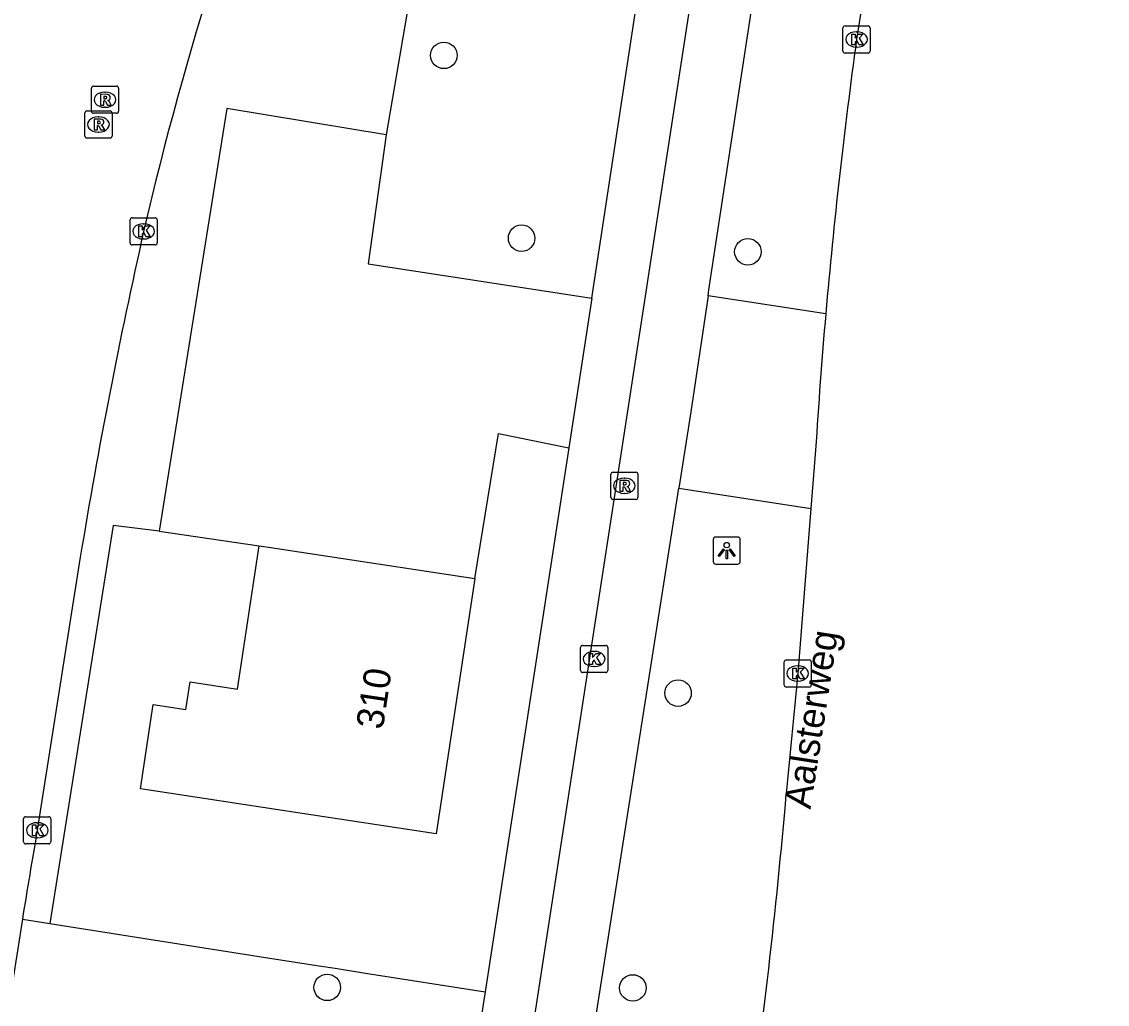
# Model space of a CAD drawing. Extents: x 161094 to 161705, y 379509 to 380907.
# Drawn here: x 161594.33 to 161634.35, y 380358.54 to 380394.77 of the extents above; entities that cross this region are included whole.
import ezdxf

# ---------------------------------------------------------------- set-up
doc = ezdxf.new("R2010")
doc.units = 0
for name, color, linetype in [('IMGEO_Berm_groen', 7, 'Continuous'), ('IMGEO_Boom', 7, 'Continuous'), ('IMGEO_Fietspad_gesloten', 7, 'Continuous'), ('IMGEO_Kolk', 7, 'Continuous'), ('IMGEO_Lichtpunt', 7, 'Continuous'), ('IMGEO_Openbare_ruimte_label', 7, 'Continuous'), ('IMGEO_OVBaan_gesloten', 7, 'Continuous'), ('IMGEO_Pand', 7, 'Continuous'), ('IMGEO_Pand_nummerreeks', 7, 'Continuous'), ('IMGEO_Parkeervlak_open', 7, 'Continuous'), ('IMGEO_Rijbaan_lokaal_open', 7, 'Continuous'), ('IMGEO_Rijbaan_regionaal_gesloten', 7, 'Continuous'), ('IMGEO_Rioolput', 7, 'Continuous'), ('IMGEO_Voetpad_open', 7, 'Continuous')]:
    doc.layers.add(name, color=color, linetype=linetype)

msp = doc.modelspace()

# ---------------------------------------------------------------- linework, layer by layer
at = {"layer": 'IMGEO_Berm_groen'}
for points in [[(161613.791, 380425.771), (161607.762, 380390.596)], [(161599.392, 380375.982), (161597.696, 380376.197), (161595.362, 380361.521)], [(161594.355, 380361.681), (161595.362, 380361.521)], [(161595.362, 380361.521), (161603.085, 380360.307), (161605.209, 380359.973), (161605.886, 380359.866), (161606.999, 380359.691), (161611.414, 380358.997)]]:
    msp.add_lwpolyline(points, dxfattribs=at)
at = {"layer": 'IMGEO_Boom'}
for centre in [(161609.893, 380393.524), (161612.76, 380386.784), (161621.103, 380386.282), (161618.528, 380370.013), (161605.594, 380359.163), (161616.859, 380359.142)]:
    msp.add_circle(centre, 0.489, dxfattribs=at)
at = {"layer": 'IMGEO_Fietspad_gesloten'}
for points in [[(161610.539, 380340.52), (161610.562, 380340.668), (161611.943, 380349.647), (161622.87, 380420.7), (161623.371, 380423.923)], [(161619.636, 380384.663), (161619.668, 380384.881), (161622.43, 380403.035), (161622.852, 380405.923), (161625.07, 380420.051), (161625.649, 380423.882)], [(161608.177, 380310.609), (161612.498, 380338.392), (161614.175, 380349.387), (161615.522, 380358.208), (161618.561, 380377.574)]]:
    msp.add_lwpolyline(points, dxfattribs=at)
at = {"layer": 'IMGEO_Kolk'}
for p, q in [((161624.683, 380394.611), (161625.535, 380394.611)), ((161624.608, 380393.685), (161624.608, 380394.537)), ((161625.096, 380394.391), (161625.121, 380394.391)), ((161625.609, 380394.537), (161625.609, 380393.685)), ((161625.119, 380393.831), (161625.094, 380393.831)), ((161625.535, 380393.611), (161624.683, 380393.611)), ((161598.324, 380386.609), (161598.324, 380387.461)), ((161598.399, 380387.535), (161599.251, 380387.535)), ((161599.325, 380387.461), (161599.325, 380386.609)), ((161598.812, 380387.315), (161598.837, 380387.315)), ((161598.835, 380386.755), (161598.81, 380386.755)), ((161599.251, 380386.535), (161598.399, 380386.535)), ((161615.008, 380371.772), (161615.86, 380371.772)), ((161614.933, 380370.846), (161614.933, 380371.698)), ((161615.421, 380371.552), (161615.446, 380371.552)), ((161615.934, 380371.698), (161615.934, 380370.846)), ((161615.444, 380370.992), (161615.419, 380370.992)), ((161622.44, 380370.31), (161622.44, 380371.162)), ((161622.515, 380371.236), (161623.367, 380371.236)), ((161622.928, 380371.016), (161622.953, 380371.016)), ((161623.441, 380371.162), (161623.441, 380370.31)), ((161615.86, 380370.772), (161615.008, 380370.772)), ((161623.367, 380370.236), (161622.515, 380370.236)), ((161622.951, 380370.456), (161622.926, 380370.456)), ((161594.401, 380364.528), (161594.401, 380365.38)), ((161594.476, 380365.454), (161595.328, 380365.454)), ((161595.402, 380365.38), (161595.402, 380364.528)), ((161594.889, 380365.234), (161594.914, 380365.234)), ((161594.912, 380364.674), (161594.887, 380364.674)), ((161595.328, 380364.454), (161594.476, 380364.454))]:
    msp.add_line(p, q, dxfattribs=at)
for points in [[(161624.683, 380394.611), (161625.535, 380394.611)], [(161624.608, 380393.685), (161624.608, 380394.537)], [(161624.929, 380394.311), (161625.052, 380394.311), (161625.052, 380394.16), (161625.182, 380394.311), (161625.346, 380394.311), (161625.2, 380394.16), (161625.353, 380393.911), (161625.201, 380393.911), (161625.116, 380394.075), (161625.052, 380394.008), (161625.052, 380393.911), (161624.929, 380393.911), (161624.929, 380394.311)], [(161625.609, 380394.537), (161625.609, 380393.685)], [(161625.535, 380393.611), (161624.683, 380393.611)], [(161598.324, 380386.609), (161598.324, 380387.461)], [(161598.399, 380387.535), (161599.251, 380387.535)], [(161599.325, 380387.461), (161599.325, 380386.609)], [(161598.645, 380387.235), (161598.768, 380387.235), (161598.768, 380387.084), (161598.898, 380387.235), (161599.062, 380387.235), (161598.916, 380387.084), (161599.069, 380386.835), (161598.917, 380386.835), (161598.832, 380386.999), (161598.768, 380386.932), (161598.768, 380386.835), (161598.645, 380386.835), (161598.645, 380387.235)], [(161599.251, 380386.535), (161598.399, 380386.535)], [(161615.008, 380371.772), (161615.86, 380371.772)], [(161614.933, 380370.846), (161614.933, 380371.698)], [(161615.254, 380371.472), (161615.377, 380371.472), (161615.377, 380371.321), (161615.507, 380371.472), (161615.671, 380371.472), (161615.525, 380371.321), (161615.678, 380371.072), (161615.526, 380371.072), (161615.441, 380371.236), (161615.377, 380371.169), (161615.377, 380371.072), (161615.254, 380371.072), (161615.254, 380371.472)], [(161615.934, 380371.698), (161615.934, 380370.846)], [(161622.44, 380370.31), (161622.44, 380371.162)], [(161622.515, 380371.236), (161623.367, 380371.236)], [(161623.441, 380371.162), (161623.441, 380370.31)], [(161615.86, 380370.772), (161615.008, 380370.772)], [(161622.761, 380370.936), (161622.884, 380370.936), (161622.884, 380370.785), (161623.014, 380370.936), (161623.178, 380370.936), (161623.032, 380370.785), (161623.185, 380370.536), (161623.033, 380370.536), (161622.948, 380370.7), (161622.884, 380370.633), (161622.884, 380370.536), (161622.761, 380370.536), (161622.761, 380370.936)], [(161623.367, 380370.236), (161622.515, 380370.236)], [(161594.401, 380364.528), (161594.401, 380365.38)], [(161594.476, 380365.454), (161595.328, 380365.454)], [(161595.402, 380365.38), (161595.402, 380364.528)], [(161594.722, 380365.154), (161594.845, 380365.154), (161594.845, 380365.003), (161594.975, 380365.154), (161595.139, 380365.154), (161594.993, 380365.003), (161595.146, 380364.754), (161594.994, 380364.754), (161594.909, 380364.918), (161594.845, 380364.851), (161594.845, 380364.754), (161594.722, 380364.754), (161594.722, 380365.154)], [(161595.328, 380364.454), (161594.476, 380364.454)]]:
    msp.add_lwpolyline(points, dxfattribs=at)
for centre, start, end in [((161624.685, 380394.535), 91.552, 178.448), ((161624.685, 380394.535), 91.552, 178.448), ((161625.533, 380394.535), 1.552, 88.448), ((161625.533, 380394.535), 1.552, 88.448), ((161624.685, 380393.687), 181.552, 268.448), ((161624.685, 380393.687), 181.552, 268.448), ((161625.533, 380393.687), 271.552, 358.448), ((161625.533, 380393.687), 271.552, 358.448), ((161598.401, 380387.459), 91.552, 178.448), ((161598.401, 380387.459), 91.552, 178.448), ((161599.249, 380387.459), 1.552, 88.448), ((161599.249, 380387.459), 1.552, 88.448), ((161598.401, 380386.611), 181.552, 268.448), ((161598.401, 380386.611), 181.552, 268.448), ((161599.249, 380386.611), 271.552, 358.448), ((161599.249, 380386.611), 271.552, 358.448), ((161615.01, 380371.696), 91.552, 178.448), ((161615.01, 380371.696), 91.552, 178.448), ((161615.858, 380371.696), 1.552, 88.448), ((161615.858, 380371.696), 1.552, 88.448), ((161622.517, 380371.16), 91.552, 178.448), ((161622.517, 380371.16), 91.552, 178.448), ((161623.365, 380371.16), 1.552, 88.448), ((161623.365, 380371.16), 1.552, 88.448), ((161615.01, 380370.848), 181.552, 268.448), ((161615.01, 380370.848), 181.552, 268.448), ((161615.858, 380370.848), 271.552, 358.448), ((161615.858, 380370.848), 271.552, 358.448), ((161622.517, 380370.312), 181.552, 268.448), ((161622.517, 380370.312), 181.552, 268.448), ((161623.365, 380370.312), 271.552, 358.448), ((161623.365, 380370.312), 271.552, 358.448), ((161594.478, 380365.378), 91.552, 178.448), ((161594.478, 380365.378), 91.552, 178.448), ((161595.326, 380365.378), 1.552, 88.448), ((161595.326, 380365.378), 1.552, 88.448), ((161594.478, 380364.53), 181.552, 268.448), ((161594.478, 380364.53), 181.552, 268.448), ((161595.326, 380364.53), 271.552, 358.448), ((161595.326, 380364.53), 271.552, 358.448)]:
    msp.add_arc(centre, 0.0765, start, end, dxfattribs=at)
for centre, major_axis, ratio, start_param, end_param in [((161625.095, 380394.111), (-0.387, 0.002), 0.722429, 4.712389, 7.853982), ((161625.12, 380394.111), (-0.39, 0.002), 0.717154, 1.570796, 4.712389), ((161598.811, 380387.035), (-0.387, 0.002), 0.722429, 4.712389, 7.853982), ((161598.836, 380387.035), (-0.39, 0.002), 0.717154, 1.570796, 4.712389), ((161615.42, 380371.272), (-0.387, 0.002), 0.722429, 4.712389, 7.853982), ((161615.445, 380371.272), (-0.39, 0.002), 0.717154, 1.570796, 4.712389), ((161622.927, 380370.736), (-0.387, 0.002), 0.722429, 4.712389, 7.853982), ((161622.952, 380370.736), (-0.39, 0.002), 0.717154, 1.570796, 4.712389), ((161594.888, 380364.954), (-0.387, 0.002), 0.722429, 4.712389, 7.853982), ((161594.913, 380364.954), (-0.39, 0.002), 0.717154, 1.570796, 4.712389)]:
    msp.add_ellipse(centre, major_axis=major_axis, ratio=ratio, start_param=start_param, end_param=end_param, dxfattribs=at)
at = {"layer": 'IMGEO_Lichtpunt'}
for p, q in [((161620.726, 380375.766), (161619.918, 380375.766)), ((161620.726, 380375.766), (161619.918, 380375.766)), ((161619.824, 380375.671), (161619.824, 380374.864)), ((161619.824, 380375.671), (161619.824, 380374.864)), ((161620.82, 380374.864), (161620.82, 380375.671)), ((161620.82, 380374.864), (161620.82, 380375.671)), ((161619.918, 380374.77), (161620.726, 380374.77)), ((161619.918, 380374.77), (161620.726, 380374.77))]:
    msp.add_line(p, q, dxfattribs=at)
for points in [[(161620.198, 380375.335), (161620.237, 380375.307), (161620.049, 380375.045), (161620.011, 380375.072), (161620.198, 380375.335)], [(161620.3, 380375.287), (161620.347, 380375.287), (161620.347, 380374.965), (161620.3, 380374.965), (161620.3, 380375.287)], [(161620.41, 380375.307), (161620.448, 380375.334), (161620.635, 380375.072), (161620.596, 380375.044), (161620.41, 380375.307)]]:
    msp.add_lwpolyline(points, dxfattribs=at)
msp.add_circle((161620.323, 380375.469), 0.0994, dxfattribs=at)
for centre, start, end in [((161619.918, 380375.671), 90, 180), ((161619.918, 380375.671), 90, 180), ((161620.726, 380375.671), 0, 90), ((161620.726, 380375.671), 0, 90), ((161619.918, 380374.864), 180, 270), ((161619.918, 380374.864), 180, 270), ((161620.726, 380374.864), 270, 0), ((161620.726, 380374.864), 270, 360)]:
    msp.add_arc(centre, 0.0946, start, end, dxfattribs=at)
at = {"layer": 'IMGEO_OVBaan_gesloten'}
msp.add_lwpolyline([(161596.489, 380375.019), (161594.902, 380364.954)], dxfattribs=at)
for centre, radius, start, end in [((161724.132, 380357.942), 128.64, 157.92248, 166.90854), ((161805.867, 380340.551), 212.197, 167.33371, 170.65183), ((161833.983, 380323.315), 242.679, 170.1204, 170.90386), ((161822.075, 380325.281), 230.611, 170.91846, 174.05141)]:
    msp.add_arc(centre, radius, start, end, dxfattribs=at)
at = {"layer": 'IMGEO_Pand'}
for points in [[(161611.039, 380374.237), (161609.609, 380364.827), (161604.666, 380365.578), (161598.703, 380366.485), (161599.175, 380369.59), (161600.385, 380369.406), (161600.541, 380370.428), (161602.284, 380370.163), (161603.087, 380375.446)], [(161603.087, 380375.446), (161603.426, 380375.395), (161606.096, 380374.989), (161611.039, 380374.237)]]:
    msp.add_lwpolyline(points, dxfattribs=at)
at = {"layer": 'IMGEO_Parkeervlak_open'}
for points in [[(161607.762, 380390.596), (161601.896, 380391.571), (161599.392, 380375.982)], [(161607.762, 380390.596), (161607.104, 380385.838), (161615.349, 380384.57)], [(161611.039, 380374.237), (161611.904, 380379.584), (161614.501, 380379.058)], [(161599.392, 380375.982), (161603.087, 380375.446)]]:
    msp.add_lwpolyline(points, dxfattribs=at)
at = {"layer": 'IMGEO_Rijbaan_lokaal_open'}
for points in [[(161619.636, 380384.663), (161619.001, 380380.379), (161618.561, 380377.574)], [(161623.975, 380383.998), (161619.636, 380384.663)], [(161618.561, 380377.574), (161623.428, 380376.818)]]:
    msp.add_lwpolyline(points, dxfattribs=at)
at = {"layer": 'IMGEO_Rijbaan_regionaal_gesloten'}
for points in [[(161634.353, 380453.162), (161633.68, 380448.786), (161631.601, 380435.492), (161631.236, 380433.142), (161629.075, 380419.224), (161628.145, 380413.237), (161625.109, 380394.111)], [(161629.075, 380419.224), (161628.145, 380413.237), (161625.109, 380394.111)], [(161623.6, 380378.975), (161623.428, 380376.818), (161622.941, 380370.736), (161622.517, 380366.313)], [(161623.6, 380378.975), (161623.428, 380376.818)], [(161623.428, 380376.818), (161622.941, 380370.736), (161622.517, 380366.313)]]:
    msp.add_lwpolyline(points, dxfattribs=at)
for centre, radius, start, end in [((161827.799, 380366.263), 204.594, 172.17691, 175.02706), ((161827.799, 380366.263), 204.594, 172.17691, 175.02706), ((161826.918, 380366.321), 203.712, 175.02205, 176.43878), ((161826.918, 380366.321), 203.712, 175.02205, 176.43878), ((161415.48, 380383.836), 207.778, 351.58062, 355.1621), ((161415.48, 380383.836), 207.778, 351.58062, 355.1621)]:
    msp.add_arc(centre, radius, start, end, dxfattribs=at)
at = {"layer": 'IMGEO_Rioolput'}
for p, q in [((161596.9, 380391.463), (161596.9, 380392.315)), ((161596.975, 380392.389), (161597.827, 380392.389)), ((161597.388, 380392.169), (161597.413, 380392.169)), ((161597.901, 380392.315), (161597.901, 380391.463)), ((161596.659, 380390.55), (161596.659, 380391.402)), ((161596.734, 380391.476), (161597.586, 380391.476)), ((161597.827, 380391.389), (161596.975, 380391.389)), ((161597.411, 380391.609), (161597.386, 380391.609)), ((161597.66, 380391.402), (161597.66, 380390.55)), ((161597.147, 380391.256), (161597.172, 380391.256)), ((161597.17, 380390.696), (161597.145, 380390.696)), ((161597.586, 380390.476), (161596.734, 380390.476)), ((161616.124, 380378.156), (161616.976, 380378.156)), ((161616.049, 380377.23), (161616.049, 380378.082)), ((161616.537, 380377.936), (161616.562, 380377.936)), ((161617.05, 380378.082), (161617.05, 380377.23)), ((161616.56, 380377.376), (161616.535, 380377.376)), ((161616.976, 380377.156), (161616.124, 380377.156))]:
    msp.add_line(p, q, dxfattribs=at)
for points in [[(161596.9, 380391.463), (161596.9, 380392.315)], [(161596.975, 380392.389), (161597.827, 380392.389)], [(161597.901, 380392.315), (161597.901, 380391.463)], [(161597.489, 380392.087), (161597.237, 380392.089), (161597.237, 380391.689)], [(161597.237, 380391.689), (161597.361, 380391.689), (161597.361, 380391.851), (161597.372, 380391.851)], [(161597.415, 380392.008), (161597.361, 380392.008), (161597.361, 380391.927)], [(161597.361, 380391.927), (161597.413, 380391.927)], [(161597.419, 380391.822), (161597.49, 380391.689), (161597.63, 380391.689), (161597.565, 380391.815)], [(161596.659, 380390.55), (161596.659, 380391.402)], [(161596.734, 380391.476), (161597.586, 380391.476)], [(161597.827, 380391.389), (161596.975, 380391.389)], [(161597.66, 380391.402), (161597.66, 380390.55)], [(161597.248, 380391.174), (161596.996, 380391.176), (161596.996, 380390.776)], [(161597.174, 380391.095), (161597.12, 380391.095), (161597.12, 380391.014)], [(161597.12, 380391.014), (161597.172, 380391.014)], [(161596.996, 380390.776), (161597.12, 380390.776), (161597.12, 380390.938), (161597.131, 380390.938)], [(161597.178, 380390.909), (161597.249, 380390.776), (161597.389, 380390.776), (161597.324, 380390.902)], [(161597.586, 380390.476), (161596.734, 380390.476)], [(161616.124, 380378.156), (161616.976, 380378.156)], [(161616.049, 380377.23), (161616.049, 380378.082)], [(161616.638, 380377.854), (161616.386, 380377.856), (161616.386, 380377.456)], [(161616.564, 380377.775), (161616.51, 380377.775), (161616.51, 380377.694)], [(161617.05, 380378.082), (161617.05, 380377.23)], [(161616.386, 380377.456), (161616.51, 380377.456), (161616.51, 380377.618), (161616.521, 380377.618)], [(161616.51, 380377.694), (161616.562, 380377.694)], [(161616.568, 380377.589), (161616.639, 380377.456), (161616.779, 380377.456), (161616.714, 380377.582)], [(161616.976, 380377.156), (161616.124, 380377.156)]]:
    msp.add_lwpolyline(points, dxfattribs=at)
for centre, radius, start, end in [((161596.977, 380392.313), 0.0765, 91.552, 178.448), ((161596.977, 380392.313), 0.0765, 91.552, 178.448), ((161597.825, 380392.313), 0.0765, 1.552, 88.448), ((161597.825, 380392.313), 0.0765, 1.552, 88.448), ((161597.371, 380391.798), 0.0533, 26.0293, 88.6989), ((161597.397, 380392.116), 0.19, 274.7715, 282.9687), ((161597.421, 380391.912), 0.0964, 77.0061, 93.1865), ((161597.435, 380391.969), 0.0378, 276.6634, 79.6772), ((161597.488, 380391.977), 0.109, 350.3612, 89.416), ((161597.486, 380391.977), 0.112, 277.5842, 350.9817), ((161597.47, 380391.762), 0.108, 29.5134, 73.7905), ((161596.736, 380391.4), 0.0765, 91.552, 178.448), ((161596.736, 380391.4), 0.0765, 91.552, 178.448), ((161596.977, 380391.465), 0.0765, 181.552, 268.448), ((161596.977, 380391.465), 0.0765, 181.552, 268.448), ((161597.584, 380391.4), 0.0765, 1.552, 88.448), ((161597.584, 380391.4), 0.0765, 1.552, 88.448), ((161597.825, 380391.465), 0.0765, 271.552, 358.448), ((161597.825, 380391.465), 0.0765, 271.552, 358.448), ((161597.156, 380391.203), 0.19, 274.7715, 282.9687), ((161597.18, 380390.999), 0.0964, 77.0061, 93.1865), ((161597.194, 380391.056), 0.0378, 276.6634, 79.6772), ((161597.247, 380391.064), 0.109, 350.3612, 89.416), ((161597.245, 380391.064), 0.112, 277.5842, 350.9817), ((161597.229, 380390.849), 0.108, 29.5134, 73.7905), ((161596.736, 380390.552), 0.0765, 181.552, 268.448), ((161596.736, 380390.552), 0.0765, 181.552, 268.448), ((161597.13, 380390.885), 0.0533, 26.0293, 88.6989), ((161597.584, 380390.552), 0.0765, 271.552, 358.448), ((161597.584, 380390.552), 0.0765, 271.552, 358.448), ((161616.126, 380378.08), 0.0765, 91.552, 178.448), ((161616.126, 380378.08), 0.0765, 91.552, 178.448), ((161616.974, 380378.08), 0.0765, 1.552, 88.448), ((161616.974, 380378.08), 0.0765, 1.552, 88.448), ((161616.57, 380377.679), 0.0964, 77.0061, 93.1865), ((161616.584, 380377.736), 0.0378, 276.6634, 79.6772), ((161616.637, 380377.744), 0.109, 350.3612, 89.416), ((161616.52, 380377.565), 0.0533, 26.0293, 88.6989), ((161616.546, 380377.883), 0.19, 274.7715, 282.9687), ((161616.635, 380377.744), 0.112, 277.5842, 350.9817), ((161616.619, 380377.529), 0.108, 29.5134, 73.7905), ((161616.126, 380377.232), 0.0765, 181.552, 268.448), ((161616.126, 380377.232), 0.0765, 181.552, 268.448), ((161616.974, 380377.232), 0.0765, 271.552, 358.448), ((161616.974, 380377.232), 0.0765, 271.552, 358.448)]:
    msp.add_arc(centre, radius, start, end, dxfattribs=at)
for centre, major_axis, ratio, start_param, end_param in [((161597.387, 380391.889), (-0.387, 0.002), 0.722429, 4.712389, 7.853982), ((161597.412, 380391.889), (-0.39, 0.002), 0.717154, 1.570796, 4.712389), ((161597.146, 380390.976), (-0.387, 0.002), 0.722429, 4.712389, 7.853982), ((161597.171, 380390.976), (-0.39, 0.002), 0.717154, 1.570796, 4.712389), ((161616.536, 380377.656), (-0.387, 0.002), 0.722429, 4.712389, 7.853982), ((161616.561, 380377.656), (-0.39, 0.002), 0.717154, 1.570796, 4.712389)]:
    msp.add_ellipse(centre, major_axis=major_axis, ratio=ratio, start_param=start_param, end_param=end_param, dxfattribs=at)
at = {"layer": 'IMGEO_Voetpad_open'}
for points in [[(161615.349, 380384.57), (161621.441, 380424.641)], [(161615.349, 380384.57), (161614.501, 380379.058)], [(161614.501, 380379.058), (161611.414, 380358.997)], [(161611.414, 380358.997), (161608.555, 380340.78), (161610.539, 380340.52)]]:
    msp.add_lwpolyline(points, dxfattribs=at)

# ---------------------------------------------------------------- texts
at = {"layer": 'IMGEO_Openbare_ruimte_label'}
msp.add_text('Aalsterweg', height=1, rotation=81.084, dxfattribs=at).set_placement((161623.408, 380365.711))
at = {"layer": 'IMGEO_Pand_nummerreeks'}
msp.add_text('310', height=1, rotation=81.3591, dxfattribs=at).set_placement((161607.64, 380368.642))

doc.saveas('drawing.dxf')
